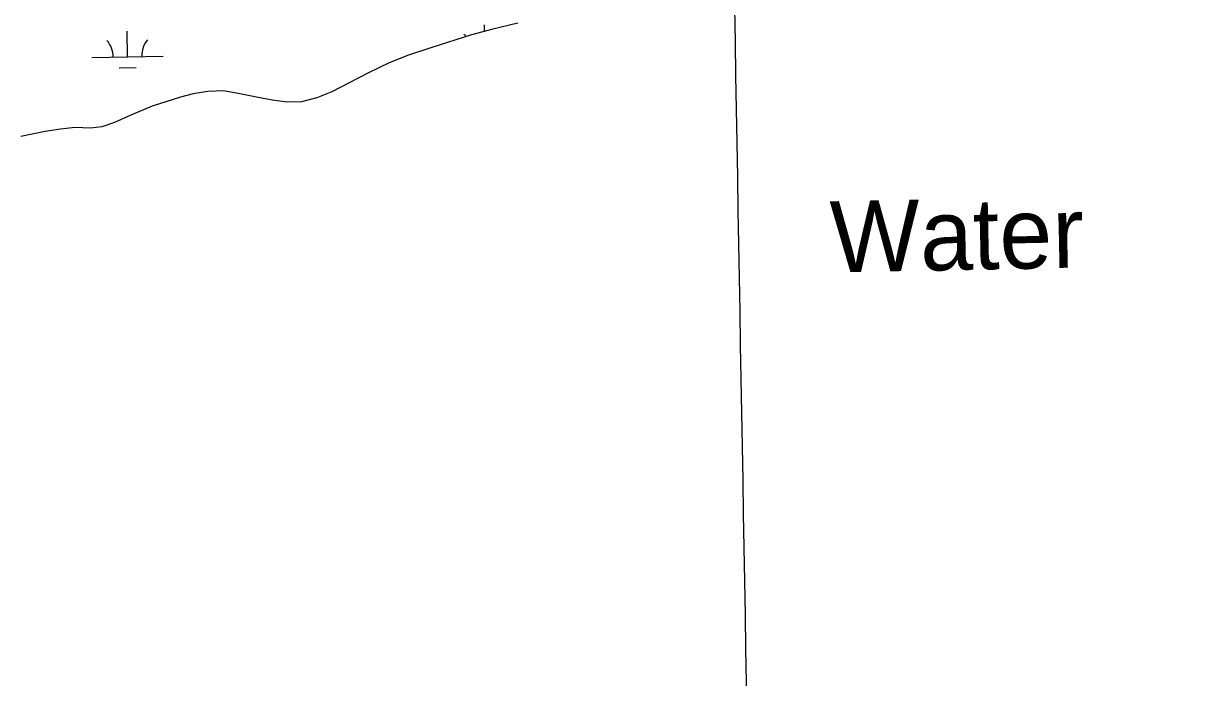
# Model space of a CAD drawing. Extents: x 3892998 to 3931244, y 278583 to 304547.
# Drawn here: x 3917313 to 3918947, y 295276 to 296194 of the extents above; entities that cross this region are included whole.
import ezdxf

# ---------------------------------------------------------------- set-up
doc = ezdxf.new("R2010")
doc.units = 0
for name, color, linetype in [('V-GRID-MAJR', 7, 'Continuous'), ('V-RIVR-IDEN', 7, 'Continuous'), ('V-TOPO-SHOR', 7, 'Continuous'), ('V-WETL-SWMP', 7, 'Continuous')]:
    doc.layers.add(name, color=color, linetype=linetype)

msp = doc.modelspace()

# ---------------------------------------------------------------- linework, layer by layer
at = {"layer": 'V-GRID-MAJR'}
for points in [[(3918519.216, 284383.145), (3918413.491, 290439.973), (3918307.7120000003, 296499.886), (3918201.934, 302559.792), (3918201.88, 302562.882)], [(3897060.6180000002, 296135.19), (3902372.4110000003, 296225.205), (3907684.191, 296315.993), (3912995.9590000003, 296407.553), (3918307.7120000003, 296499.886), (3923619.453, 296592.991), (3928931.179, 296686.869), (3928931.18, 296686.869)]]:
    msp.add_spline(points, degree=3, dxfattribs=at)
at = {"layer": 'V-TOPO-SHOR'}
msp.add_lwpolyline([(3918007.9960000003, 296194.749), (3917972.893, 296186.342), (3917942.745, 296178.48600000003), (3917887.373, 296160.359), (3917854.23, 296149.759), (3917827.223, 296139.105), (3917798.4080000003, 296125.105), (3917771.169, 296110.693), (3917746.722, 296098.434), (3917725.669, 296089.908), (3917704.2490000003, 296084.352), (3917684.6520000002, 296083.926), (3917663.103, 296086.48600000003), (3917638.6, 296091.051), (3917617.662, 296095.583), (3917594.54, 296099.544), (3917572.7630000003, 296098.741), (3917551.759, 296095.556), (3917534.304, 296090.957), (3917494.61, 296078.038), (3917464.619, 296065.43), (3917441.572, 296055.139), (3917423.511, 296049.159), (3917407.86, 296047.314), (3917386.2970000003, 296048.094), (3917365.495, 296045.7), (3917344.292, 296042.517), (3917309.995, 296035.685)], dxfattribs=at)
at = {"layer": 'V-WETL-SWMP'}
for p, q in [((3917961.12086207, 296183.27550470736), (3917960.9668544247, 296192.1724557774)), ((3917459.757106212, 296147.4910417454), (3917459.1340337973, 296183.48564940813)), ((3917409.7645955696, 296146.6256633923), (3917509.749616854, 296148.35642009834)), ((3917448.025976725, 296131.8546623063), (3917472.022381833, 296132.27004391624))]:
    msp.add_line(p, q, dxfattribs=at)
msp.add_lwpolyline([(3918007.995, 296194.749), (3917972.893, 296186.343), (3917942.744, 296178.487), (3917887.372, 296160.359), (3917854.23, 296149.759), (3917827.223, 296139.106), (3917798.407, 296125.104), (3917771.17, 296110.693), (3917746.722, 296098.434), (3917725.67, 296089.907), (3917704.2490000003, 296084.352), (3917684.6520000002, 296083.926), (3917663.102, 296086.48600000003), (3917638.6010000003, 296091.05), (3917617.662, 296095.58400000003), (3917594.54, 296099.543), (3917572.764, 296098.74), (3917551.758, 296095.556), (3917534.3030000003, 296090.956), (3917494.61, 296078.037), (3917464.6180000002, 296065.43), (3917441.572, 296055.139), (3917423.512, 296049.159), (3917407.861, 296047.314), (3917386.296, 296048.093), (3917365.495, 296045.699), (3917344.292, 296042.517), (3917309.995, 296035.686)], dxfattribs=at)
for centre, radius, start, end in [((3917404.5142271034, 296147.00965298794), 35.24628790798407, 0.21988000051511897, 41.76353833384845), ((3917514.983549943, 296148.9218946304), 35.246287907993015, 140.21987699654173, 181.76353532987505), ((3917906.3470477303, 296155.6964593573), 35.24628790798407, 35.17857390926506, 41.76353833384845)]:
    msp.add_arc(centre, radius, start, end, dxfattribs=at)

# ---------------------------------------------------------------- texts
at = {"layer": 'V-RIVR-IDEN'}
msp.add_text('Water', height=99.99980199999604, rotation=1.1584721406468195, dxfattribs=at).set_placement((3918447.440527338, 295844.51525034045))

doc.saveas('drawing.dxf')
